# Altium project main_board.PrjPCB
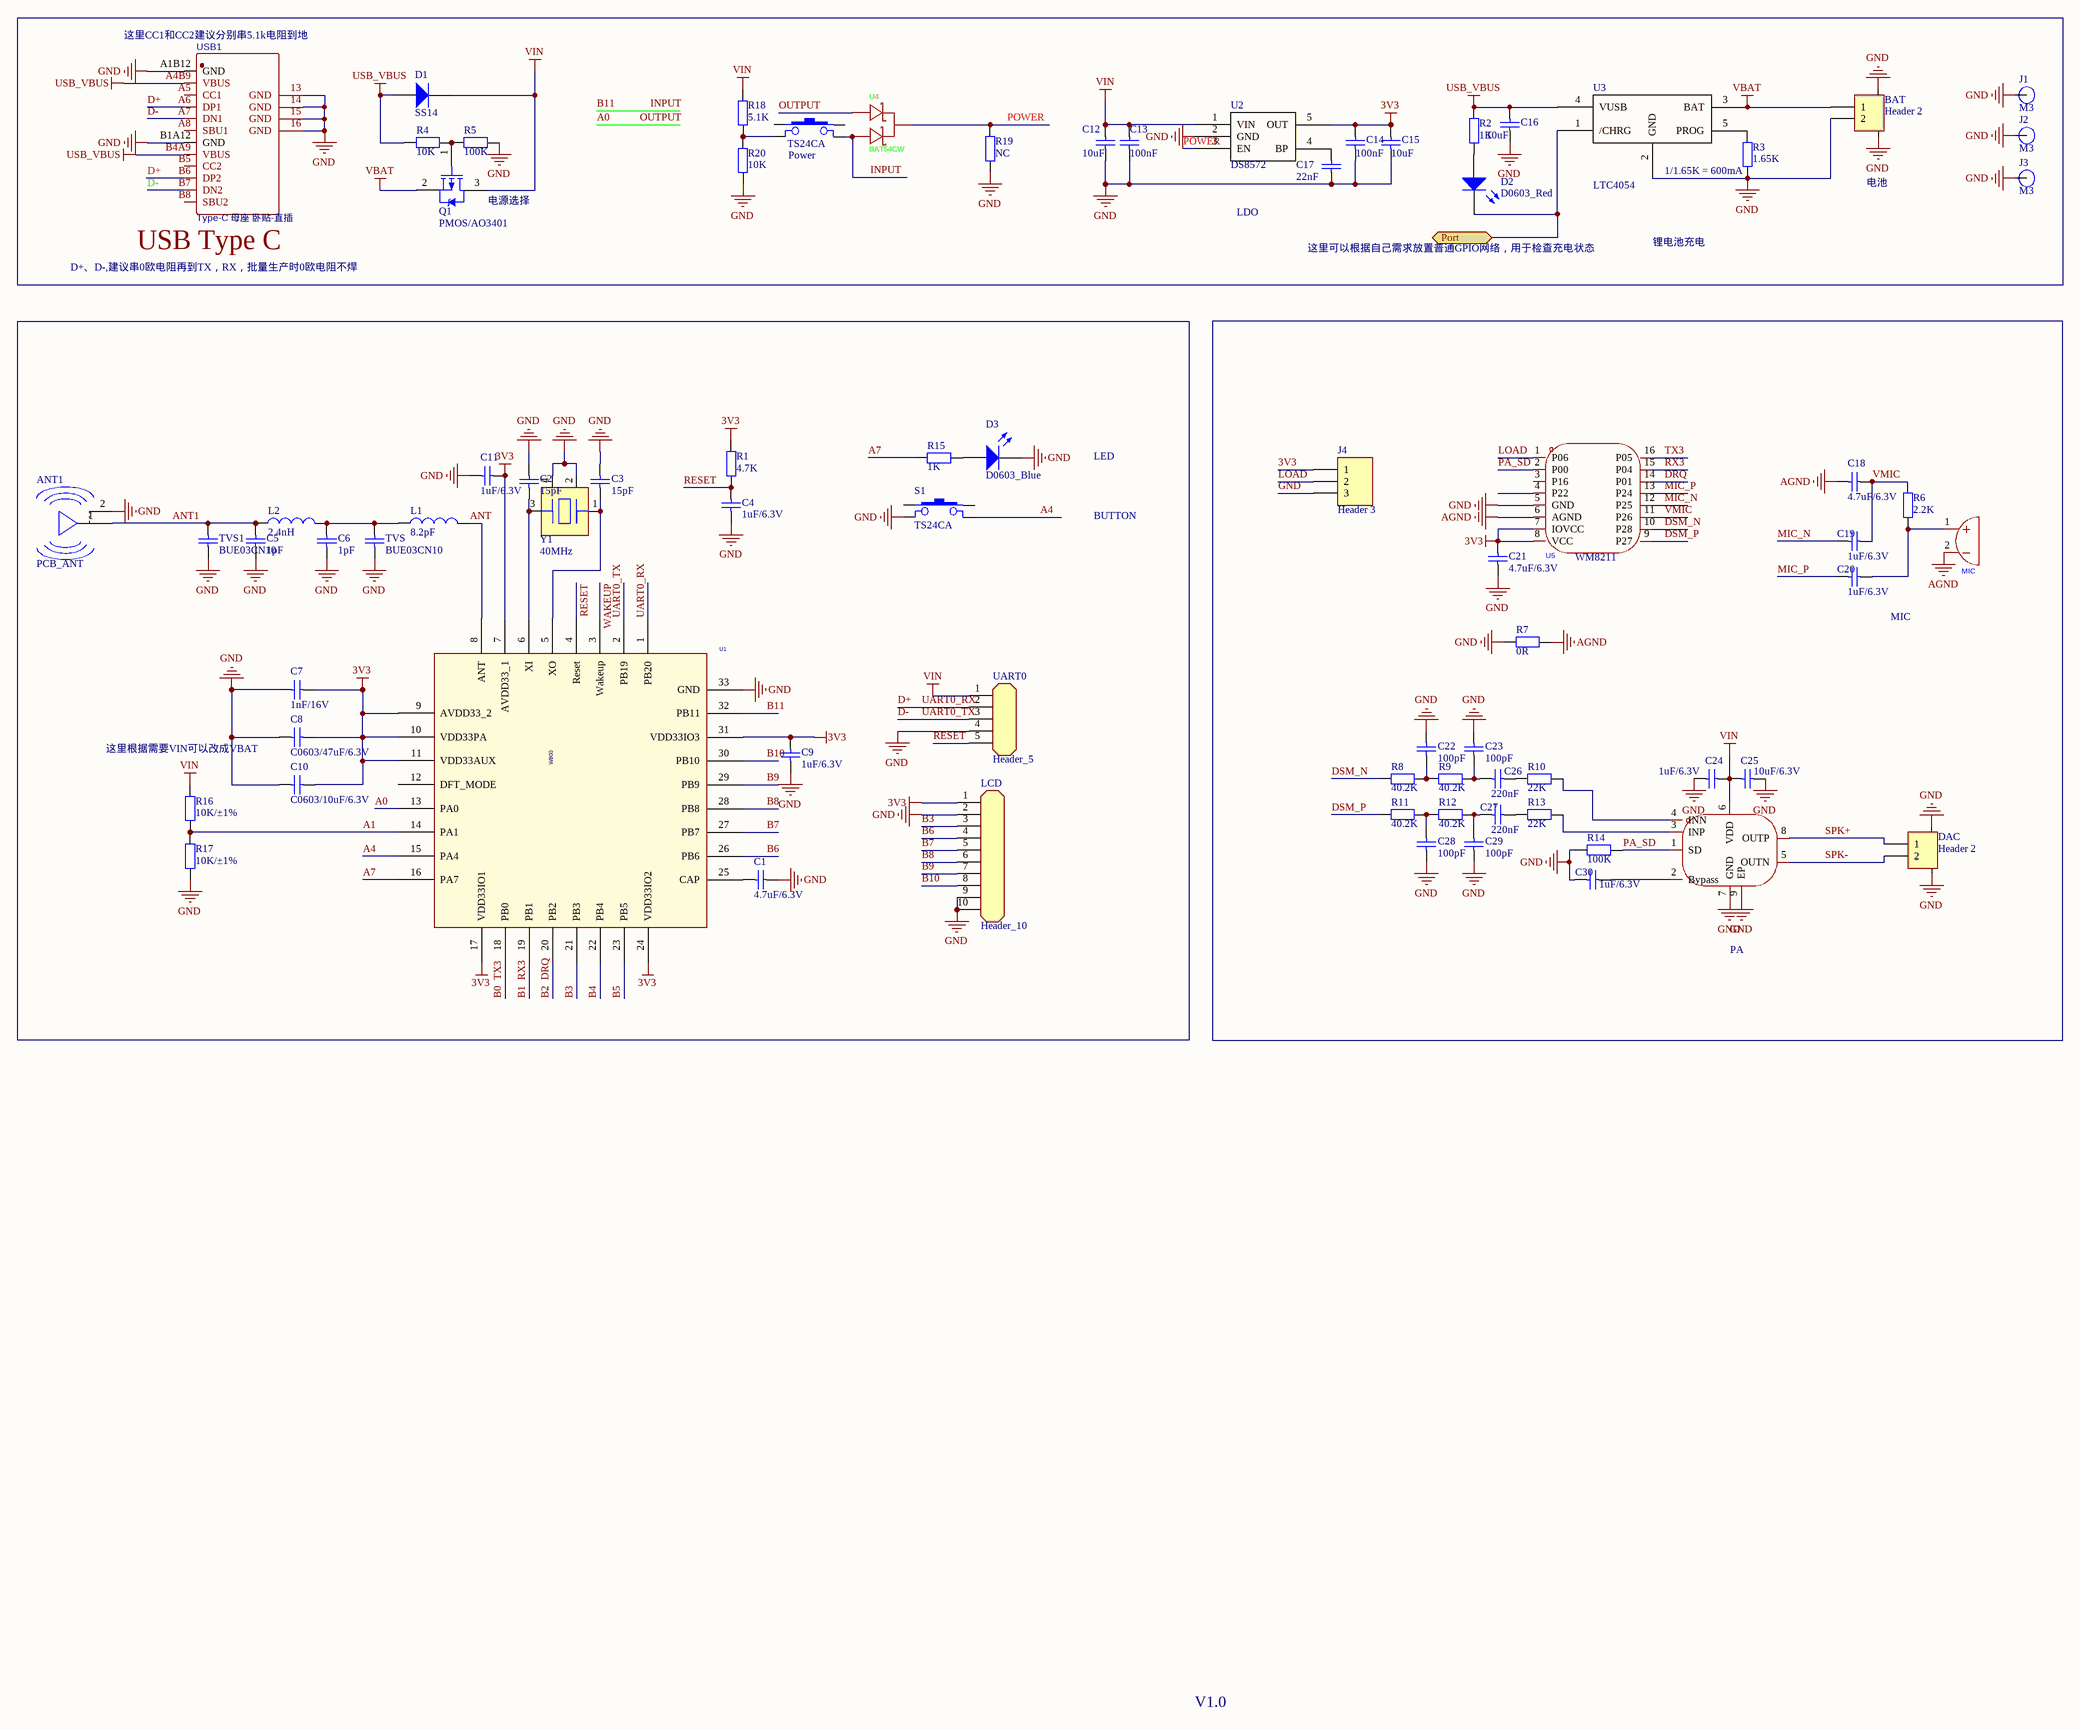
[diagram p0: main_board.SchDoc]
1 sheet, 78 parts. Net scope: flat (ports and power ports of the same name join across sheets).
Board file: main_board.PcbDoc

## Sheet main_board.SchDoc
size A2

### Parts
ANT1  PCB_ANT  [MINI_ANT]
BAT  Header 2  [CONN-SMD_2P-P1.25-HC-1.25-2PWT]
C1  4.7uF/6.3V  [C0402]
C2  15pF  [C0402]
C3  15pF  [C0402]
C4  1uF/6.3V  [C0402]
C5  1pF  [C0402]
C6  1pF  [C0402]
C7  1nF/16V  [C0402]
C8  C0603/47uF/6.3V  [C0603]
C9  1uF/6.3V  [C0402]
C10  C0603/10uF/6.3V  [C0603]
C11  1uF/6.3V  [C0402]
C12  10uF  [C0402]
C13  100nF  [C0402]
C14  100nF  [C0402]
C15  10uF  [C0402]
C16  10uF  [C0402]
C17  22nF  [C0402]
C18  4.7uF/6.3V  [C0402]
C19  1uF/6.3V  [C0402]
C20  1uF/6.3V  [C0402]
C21  4.7uF/6.3V  [C0402]
C22  100pF  [C0402]
C23  100pF  [C0402]
C24  1uF/6.3V  [C0402]
C25  10uF/6.3V  [C0402]
C26  220nF  [C0402]
C27  220nF  [C0402]
C28  100pF  [C0402]
C29  100pF  [C0402]
C30  1uF/6.3V  [C0402]
D1  SS14  [DO-214]
D2  D0603_Red  [D0603]
D3  D0603_Blue  [D0603]
DAC  Header 2  [CONN-SMD_2P-P1.25-HC-1.25-2PWT]
J1  M3  [M3 125X200]
J2  M3  [M3 125X200]
J3  M3  [M3 125X200]
J4  Header 3  [HDR1X3]
L1  8.2pF  [0402C]
L2  2.4nH  [0402C]
LCD  Header_10  [CONN-SMD_SM08B-GHS-TB-LF-SN]
MIC  GMI6027P-2C30DB  [MIC-TH_BD6.0-P1.90-D0.4-L]  (value not drawn)
Power  TS24CA  [SW-SMD_TS24CA]
Q1  PMOS/AO3401  [SOT-23]
R1  4.7K  [R0402]
R2  1K  [R0402]
R3  1.65K  [R0402]
R4  10K  [R0402]
R5  100K  [R0402]
R6  2.2K  [R0402]
R7  0R  [R0402]
R8  40.2K  [R0402]
R9  40.2K  [R0402]
R10  22K  [R0402]
R11  40.2K  [R0402]
R12  40.2K  [R0402]
R13  22K  [R0402]
R14  100K  [R0402]
R15  1K  [R0402]
R16  10K/±1%  [R0402]
R17  10K/±1%  [R0402]
R18  5.1K  [R0402]
R19  NC  [R0402]
R20  10K  [R0402]
S1  TS24CA  [SW-SMD_TS24CA]
TVS  BUE03CN10  [C0402]
TVS1  BUE03CN10  [C0402]
U1  W800  [QFN32_4X4]
U2  DS8572  [SOT-23-5]
U3  LTC4054  [SOT-23-5]
U4  BAT54CW  [SOT-323-3_L2.0-W1.3-P1.30-LS2.3-BR]
U5  WM8211  [SOP-16]  (value not drawn)
U6  HAA9209  [DFN-8_L2.0-W2.0-P0.50-BL-EP]  (value not drawn)
UART0  Header_5  [PH_5PIN_DIP_2.54MM_180DEG]
USB1  Type-C 母座 卧贴-直插  [Type-C 母座 卧贴-直插]
Y1  40MHz  [OSC-TZ1067B]

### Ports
Port

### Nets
3V3: C7.2 C8.2 C9.2 C10.2 C11.1 C14.2 C15.2 C21.2 J4.1 LCD.1 R1.2 U1.7(AVDD33_1) U1.9(AVDD33_2) U1.10(VDD33PA) U1.11(VDD33AUX) U1.17(VDD33IO1) U1.24(VDD33IO2) U1.31(VDD33IO3) U2.5(OUT) U5.7(IOVCC) U5.8(VCC)
AGND: C18.1 MIC.2 R7.2 U5.6(AGND)
GND: ANT1.2(GND) BAT.2 BAT.3 BAT.4 C1.2 C2.1 C3.1 C4.1 C5.1 C6.1 C7.1 C8.1 C9.1 C10.1 C11.2 C12.1 C13.1 C14.1 C15.1 C16.1 C17.1 C21.1 C22.2 C23.2 C24.1 C25.2 C28.1 C29.1 C30.1 D3.2(K) DAC.3 DAC.4 J1.1(GND) J2.1(GND) J3.1(GND) J4.3 LCD.2 LCD.9 LCD.10 R3.1 R5.2 R7.1 R14.1 R17.1 R19.2 R20.2 S1.3 TVS.1 TVS1.1 U1.33(GND) U2.2(GND) U3.2(GND) U5.5(GND) U6.7(GND) U6.9(EP) UART0.4 USB1.13(GND) USB1.14(GND) USB1.15(GND) USB1.16(GND) USB1.A1B12(GND) USB1.B1A12(GND) Y1.2 Y1.4
USB_VBUS: C16.2 D1.1(A) R2.2 R4.1 U3.4(VUSB) USB1.A4B9(VBUS) USB1.B4A9(VBUS)
VBAT: BAT.1 Q1.2(S) U3.3(BAT)
VIN: C12.2 C13.2 C24.2 C25.1 D1.2(K) Q1.3(D) R16.2 R18.1 U2.1(VIN) U6.6(VDD) UART0.1
A0: U1.13(PA0) U4.1(A1)  [also labelled OUTPUT]
A1: R16.1 R17.2 U1.14(PA1)
A4: S1.4 U1.15(PA4)
A7: R15.2 U1.16(PA7)
ANT: L1.2 U1.8(ANT)
ANT1: ANT1.1(Feed) C5.2 L2.1 TVS1.2
B0: U1.18(PB0) U5.16(P05)  [also labelled TX3]
B1: U1.19(PB1) U5.15(P04)  [also labelled RX3]
B2: U1.20(PB2) U5.14(P01)  [also labelled DRQ]
B3: LCD.3 U1.21(PB3)
B4: U1.22(PB4)
B5: U1.23(PB5)
B6: LCD.4 U1.26(PB6)
B7: LCD.5 U1.27(PB7)
B8: LCD.6 U1.28(PB8)
B9: LCD.7 U1.29(PB9)
B10: LCD.8 U1.30(PB10)
B11: Power.4 U1.32(PB11) U4.2(A2)  [also labelled INPUT]
D+: U1.1(PB20) UART0.2 USB1.A6(DP1) USB1.B6(DP2)  [also labelled UART0_RX]
D-: U1.2(PB19) UART0.3 USB1.A7(DN1) USB1.B7(DN2)  [also labelled UART0_TX]
DSM_N: R8.1 U5.10(P28)
DSM_P: R11.1 U5.9(P27)
LOAD: J4.2 U5.1(P06)
MIC_N: C19.1 U5.12(P25)
MIC_P: C20.1 U5.13(P24)
PA_SD: R14.2 U5.2(P00) U6.1(SD)
POWER: R19.1 U2.3(EN) U4.3(K)
RESET: C4.2 R1.1 U1.4(Reset) UART0.5
SPK+: DAC.1 U6.8(OUTP)
SPK-: DAC.2 U6.5(OUTN)
VMIC: C18.2 C19.2 R6.2 U5.11(P26)
WAKEUP: U1.3(Wakeup)
NetC1_1: C1.1 U1.25(CAP)
NetC2_2: C2.2 U1.6(XI) Y1.3
NetC3_2: C3.2 U1.5(XO) Y1.1
NetC6_2: C6.2 L1.1 L2.2 TVS.2
NetC17_2: C17.2 U2.4(BP)
NetC20_2: C20.2 MIC.1 R6.1
NetC22_1: C22.1 R8.2 R9.1
NetC23_1: C23.1 C26.1 R9.2
NetC26_2: C26.2 R10.1
NetC27_1: C27.1 C29.2 R12.2
NetC27_2: C27.2 R13.1
NetC28_2: C28.2 R11.2 R12.1
NetC30_2: C30.2 U6.2(Bypass)
NetD2_1: D2.1(A) R2.1
NetD2_2: D2.2(K) U3.1(/CHRG) ; port Port
NetD3_1: D3.1(A) R15.1
NetPower_3: Power.3 R18.2 R20.1
NetQ1_1: Q1.1(G) R4.2 R5.1
NetR3_2: R3.2 U3.5(PROG)
NetR10_2: R10.2 U6.4(INN)
NetR13_2: R13.2 U6.3(INP)

Not connected (* = marked no-connect by the designer): Power 1 2; S1 1 2; U1 12(DFT_MODE); U5 3(P16) 4(P22); USB1 A5(CC1) A8(SBU1) B5(CC2) B8(SBU2)

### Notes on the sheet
- (near USB1) 这里CC1和CC2建议分别串5.1k电阻到地
- (near R3) 1/1.65K = 600mA
- (near Q1) 电源选择
- LDO
- 电池
- D+、D-,建议串0欧电阻再到TX，RX，批量生产时0欧电阻不焊
- (near USB1) USB Type C
- 这里可以根据自己需求放置普通GPIO网络，用于检查充电状态
- 锂电池充电
- LED
- BUTTON
- (near U5) WM8211
- (near C20) MIC
- (near R16) 这里根据需要VIN可以改成VBAT
- PA
- V1.0

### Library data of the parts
ANT1 = GPRS_PCB_ANT
BAT DAC = Header 2: Header, 2-Pin
C1 C18 C21 = C0402/4.7uF/6.3V: 01_物料名称: 电容; 02_规格参数: 贴片电容-0402-4.7UF±20%-6.3V-X5R; 04_物料编码: 10010006
C2 C3 C5 C6 TVS TVS1 = C0402/1.2pF/50V
C4 C9 C11 C19 C20 C24 C30 = C0402/1uF/6.3V: 01_物料名称: 电容; 02_规格参数: 贴片电容-0402-1UF±10%-6.3V-X5R; 04_物料编码: 10010001
C7 C17 C22 C23 C26-C29 = C0402/1nF/16V: 01_物料名称: 电容; 02_规格参数: 贴片电容-0402-1NF±10%-16V-X7R; 04_物料编码: 10010011
C8 = C0603/47uF/6.3V: 01_物料名称: 电容; 02_规格参数: 贴片电容-0603-47UF±20%-6.3V-X5R
C10 = C0603/10uF/6.3V: 01_物料名称: 电容; 02_规格参数: 贴片电容-0603-10UF±20%-6.3V-X5R; 04_物料编码: 10010012
C12 C15 C16 C25 = C0402/10uF/6.3V: 01_物料名称: 电容; 02_规格参数: 贴片电容-0402-10UF±20%-6.3V-X5R; 04_物料编码: 10010003
C13 C14 = C0402/100nF/16V: 01_物料名称: 电容; 02_规格参数: 贴片电容-0402-100NF-±10%-16V-X7R; 04_物料编码: 10010002
D1 = M7: Part Number: M7; 01_物料名称: 二极管; 02_规格参数: 贴片肖特基二极管-1N5822/SS34-3A/40V-DO-214; 04_物料编码: 10060006; Value: M7
D2 = D0603_Red: 01_物料名称: 二极管; 02_规格参数: 贴片发光二极管-红色-0603; 04_物料编码: 10060002
D3 = D0603_Blue: 01_物料名称: 二极管; 02_规格参数: 贴片发光二极管-蓝色-0603; 04_物料编码: 10060003
J1-J3 = M3: 铜柱孔; 版权归属: 源创客
J4 = Header 3: Header, 3-Pin
L1 = 2.2nH/L0402: 01_物料名称: 电感; 02_规格参数: 贴片电感-2.2NH-0402
L2 = 15nH/L0402: 01_物料名称: 电感; 02_规格参数: 贴片电感-15NH-0402
LCD = 180DIP_PH_10: 01_物料名称: 排针; 02_规格参数: 单排针 1X10P 间距2.54mm 长度11mm 直针 黑色
MIC = GMI6027P-2C30DB: Manufacturer: INGHAi(赢海); Add into BOM: yes
Q1 = AO3401/SOT-23: 01_物料名称: 场效应管; 02_规格参数: MOS管，场效应管 规格：AO3401 SOT-23 P沟道,-30V,-4.2A,55mΩ@-10V
R1 = R0402/4.7K: 01_物料名称: 贴片电阻; 02_规格参数: 贴片电阻-0402-4.7K±5%-1/16W; 04_物料编码: 10020008
R2 R15 = R0402/1K: 01_物料名称: 贴片电阻; 02_规格参数: 贴片电阻-0402-1K±5%-1/16W; 04_物料编码: NC
R3 = R0402/0R: 01_物料名称: 贴片电阻; 02_规格参数: 贴片电阻-0402-0R-±5%-1/16W; 04_物料编码: 10020002; Value: 0R
R4 = R0402/10K: 01_物料名称: 贴片电阻; 02_规格参数: 贴片电阻-0402-10K±5%-1/16W; 04_物料编码: 10020006
R5 R14 = R0402/100K: 01_物料名称: 贴片电阻; 02_规格参数: 贴片电阻-0402-100K±5%-1/16W; 04_物料编码: 10020009
R6 = R0402/2K: 01_物料名称: 贴片电阻; 02_规格参数: 贴片电阻-0402-2K±5%-1/16W; 04_物料编码: 10020012; Value: 2K
R7 = R0402/0R: 01_物料名称: 贴片电阻; 02_规格参数: 贴片电阻-0402-0R-±5%-1/16W; 04_物料编码: 10020002
R8-R13 R18-R20 = R0402/100K: 01_物料名称: 贴片电阻; 02_规格参数: 贴片电阻-0402-100K±5%-1/16W; 04_物料编码: 10020009; Value: 100K
R16 R17 = R0402/10K±1%: 01_物料名称: 贴片电阻; 02_规格参数: 贴片电阻-0402-10K±1%-1/16W
U1 = W800/QFN32: 04_物料编码: 10050003
U2 = RT9193: Part Number: JW5017F/SOT23-6; 01_物料名称: 芯片; 02_规格参数: 电源芯片-DCDCJW5017F-1.2A/26V-SOT23-6; 04_物料编码: 10050006; Value: JW5017F/SOT23-6
U4 = BAT54CW_C22392482: Manufacturer: 宏嘉诚; Add into BOM: yes; Diode Configuration: 1对共阴极; Voltage - Forward(Vf@If): 1V@100mA; Voltage - DC Reverse(Vr): 30V; Current - Rectified: 200mA; Reverse Leakage Current (Ir): 2uA@25V
U5 = WM8211: Manufacturer: TOSHIBA(东芝); Symbol: TB6612FNG,C,8,EL; Add into BOM: yes
UART0 = 180DIP_PH_5: 01_物料名称: 连接器; 02_规格参数: 单排针 1X4P  间距2.54mm 长度11mm 直针 黑色
USB1 = Type-C 母座 卧贴-直插: BOM_Manufacturer: XUNPU; BOM_Manufacturer Part: TYPEC-304-BCP16; Contributor: LCSC
Y1 = 82J0626-25MHz: X-tal 25MHz,3.2x2.5 SMD, CL=18pF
